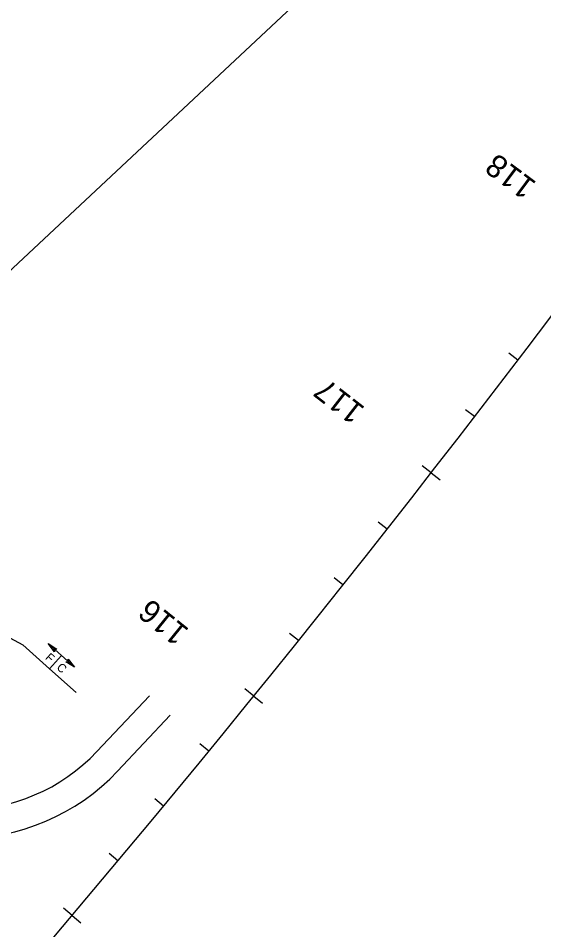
# Model space of a CAD drawing. Extents: x 2717836 to 2719883, y 337327 to 339806.
# Drawn here: x 2719104.8 to 2719289.2, y 338088.2 to 338408.2 of the extents above; entities that cross this region are included whole.
import ezdxf

# ---------------------------------------------------------------- set-up
doc = ezdxf.new("R2010")
doc.units = 0
for name, color, linetype in [('Level 1', 7, 'Continuous'), ('Level 22', 7, 'Continuous'), ('Level 23', 7, 'Continuous'), ('Level 3', 7, 'Continuous'), ('Level 31', 7, 'Continuous'), ('Level 52', 7, 'Continuous'), ('Level 6', 7, 'Continuous')]:
    doc.layers.add(name, color=color, linetype=linetype)

msp = doc.modelspace()

# ---------------------------------------------------------------- linework, layer by layer
at = {"layer": 'Level 1'}
msp.add_arc((2715303.11, 341318.59), 5000, 318.95467, 328.67948, dxfattribs=at)
at = {"layer": 'Level 22'}
for p, q in [((2719094.77, 338194.54), (2719106.38, 338188.19)), ((2719106.38, 338188.19), (2719115.77, 338179.83)), ((2719115.77, 338179.83), (2719125.16, 338171.47))]:
    msp.add_line(p, q, dxfattribs=at)
at = {"layer": 'Level 23'}
msp.add_line((2719374.17, 338574.5), (2718990.26, 338215.01), dxfattribs=at)
at = {"layer": 'Level 3'}
msp.add_line((2719158.12, 338163.49), (2719139.67, 338143.89), dxfattribs=at)
msp.add_arc((2719085.06, 338195.3), 75, 222.1604, 316.7247, dxfattribs=at)
at = {"layer": 'Level 31'}
for p, q in [((2719280.12, 338288.19), (2719276.94, 338290.62)), ((2719264.92, 338268.34), (2719261.75, 338270.78)), ((2719249.62, 338248.57), (2719246.46, 338251.03)), ((2719249.62, 338248.57), (2719252.78, 338246.12)), ((2719234.22, 338228.88), (2719231.08, 338231.35)), ((2719218.73, 338209.26), (2719215.59, 338211.75)), ((2719203.13, 338189.72), (2719200.01, 338192.23)), ((2719187.44, 338170.26), (2719184.33, 338172.78)), ((2719187.44, 338170.26), (2719190.54, 338167.74)), ((2719171.65, 338150.88), (2719168.55, 338153.41)), ((2719155.76, 338131.58), (2719152.68, 338134.13)), ((2719139.78, 338112.35), (2719136.71, 338114.92)), ((2719123.7, 338093.21), (2719120.64, 338095.79)), ((2719123.7, 338093.21), (2719126.75, 338090.63))]:
    msp.add_line(p, q, dxfattribs=at)
at = {"layer": 'Level 52'}
for p, q in [((2719115.25, 338188.65), (2719124.59, 338180.35)), ((2719115.77, 338179.83), (2719119.92, 338184.5))]:
    msp.add_line(p, q, dxfattribs=at)
for points in [[(2719115.25, 338188.65), (2719118.35, 338186.71), (2719117.27, 338186.85), (2719117.53, 338185.79)], [(2719124.59, 338180.35), (2719121.5, 338182.29), (2719122.58, 338182.14), (2719122.32, 338183.21)]]:
    msp.add_lwpolyline(points, close=True, dxfattribs=at)
at = {"layer": 'Level 6'}
msp.add_line((2719150.84, 338170.34), (2719132.39, 338150.74), dxfattribs=at)
msp.add_arc((2719085.06, 338195.3), 65, 222.1604, 316.7247, dxfattribs=at)

# ---------------------------------------------------------------- texts
at = {"layer": 'Level 31'}
for s, rotation, p in [('118', 143.2663, (2719286.98, 338350.46)), ('117', 142.1204, (2719226.82, 338271.38)), ('116', 140.9745, (2719165.1, 338193.52))]:
    msp.add_text(s, height=8, rotation=rotation, dxfattribs=at).set_placement(p)
at = {"layer": 'Level 52'}
for s, p in [('F', (2719114.02, 338183.41)), ('C', (2719118, 338179.94))]:
    msp.add_text(s, height=3, rotation=318.3448, dxfattribs=at).set_placement(p)

doc.saveas('drawing.dxf')
